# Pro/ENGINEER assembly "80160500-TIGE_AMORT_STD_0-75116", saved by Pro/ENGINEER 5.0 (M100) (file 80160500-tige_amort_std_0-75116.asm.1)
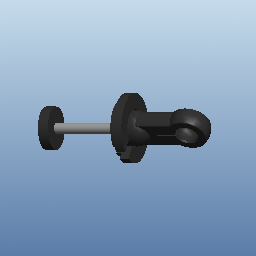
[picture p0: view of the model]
Units: millimeter Newton Second (mmNs); MM, TONNE, HOURS

Other components: 80160500-TIGE_AMORT_STD_0-75086, 80160500-COUPELLE_AMORT_STD_01

Other named items: A-DROITE, A-DESSUS, A-FACE, A-R0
